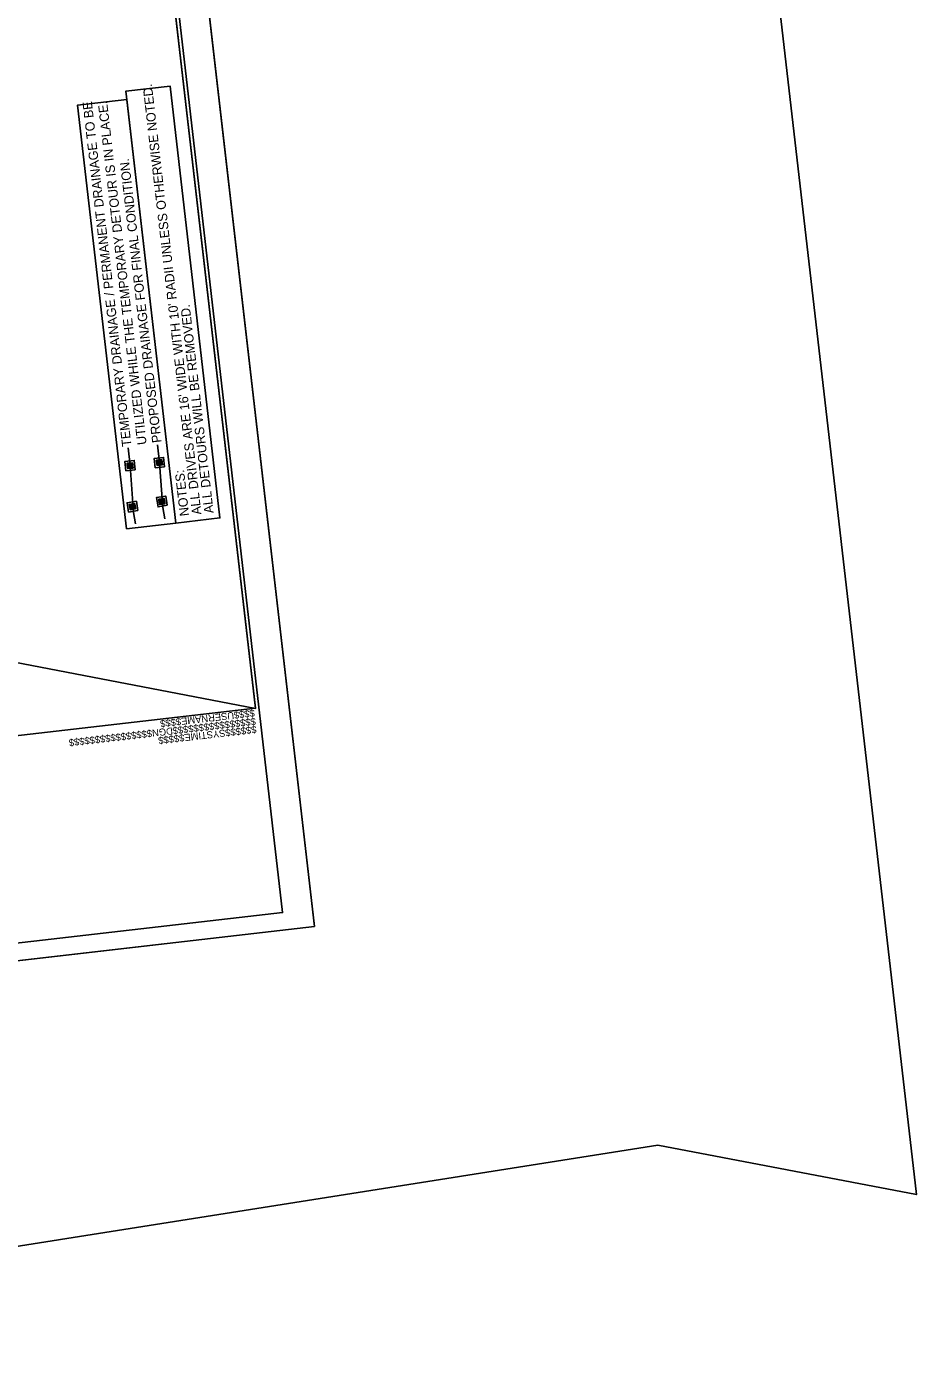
# Model space of a CAD drawing. Extents: x 477607 to 479438, y 495543 to 499482.
# Drawn here: x 478677 to 479342, y 495543 to 496535 of the extents above; entities that cross this region are included whole.
import ezdxf

# ---------------------------------------------------------------- set-up
doc = ezdxf.new("R2010")
doc.units = 0
for name, color, linetype in [('Old_Level_41', 7, 'Continuous'), ('Prop Drainage Structure CELL', 7, 'Continuous'), ('Prop DSN Text', 7, 'Continuous'), ('Prop Grid Mask', 7, 'Continuous'), ('Sheet Border Standard 30in CELL', 7, 'Continuous'), ('Sheet Cutting Line CELL', 7, 'Continuous'), ('Sheet Data Field CELL', 7, 'Continuous'), ('Sheet Layout Plan Border', 7, 'Continuous'), ('Sheet Plan CELL', 7, 'Continuous'), ('Sheet Plot Border Inside CELL', 7, 'Continuous'), ('Sheet Plot Border Outside CELL', 7, 'Continuous')]:
    doc.layers.add(name, color=color, linetype=linetype)

msp = doc.modelspace()

# ---------------------------------------------------------------- linework, layer by layer
at = {"layer": 'Old_Level_41'}
for p, q in [((478776.71, 496209.67), (478775.3, 496223.03)), ((478774.72, 496209.46), (478774.72, 496209.46)), ((478776.59, 496210.83), (478776.59, 496210.83)), ((478776.71, 496209.67), (478776.71, 496209.67)), ((478779.3, 496176.15), (478776.77, 496209.18)), ((478776.84, 496208.51), (478776.84, 496208.51)), ((478778.7, 496209.88), (478778.7, 496209.88)), ((478776.58, 496180.26), (478776.58, 496180.26)), ((478778.36, 496181.74), (478778.36, 496181.74)), ((478778.56, 496180.59), (478778.56, 496180.59)), ((478778.75, 496179.44), (478778.75, 496179.44)), ((478780.71, 496167.74), (478779.3, 496176.15)), ((478780.53, 496180.92), (478780.53, 496180.92))]:
    msp.add_line(p, q, dxfattribs=at)
for points in [[(478780.56, 496206.55), (478773.6, 496205.82), (478772.87, 496212.78), (478779.83, 496213.52)], [(478778.91, 496207.89), (478774.93, 496207.47), (478774.52, 496211.45), (478778.49, 496211.87)], [(478782.59, 496177.72), (478775.68, 496176.56), (478774.53, 496183.47), (478781.43, 496184.62)], [(478780.86, 496178.95), (478776.91, 496178.29), (478776.25, 496182.23), (478780.2, 496182.89)]]:
    msp.add_lwpolyline(points, close=True, dxfattribs=at)
for points in [[(478778.83, 496208.72), (478774.85, 496208.3), (478774.6, 496210.62), (478778.58, 496211.04), (478778.83, 496208.72)], [(478778.76, 496208.77), (478774.9, 496208.37), (478774.67, 496210.56), (478778.52, 496210.97), (478778.76, 496208.77)], [(478776.82, 496208.58), (478774.91, 496208.38), (478774.68, 496210.55), (478776.59, 496210.75), (478776.82, 496208.58)], [(478775.64, 496210.19), (478774.81, 496210.11), (478774.79, 496210.38), (478775.61, 496210.46), (478775.64, 496210.19)], [(478775.68, 496209.81), (478774.85, 496209.72), (478774.83, 496209.99), (478775.65, 496210.08), (478775.68, 496209.81)], [(478775.72, 496209.43), (478774.89, 496209.34), (478774.87, 496209.61), (478775.69, 496209.7), (478775.72, 496209.43)], [(478775.76, 496209.04), (478774.93, 496208.96), (478774.91, 496209.23), (478775.74, 496209.31), (478775.76, 496209.04)], [(478775.78, 496208.93), (478774.95, 496208.84), (478774.98, 496208.57), (478775.8, 496208.66), (478775.78, 496208.93)], [(478776.55, 496210.29), (478775.73, 496210.2), (478775.7, 496210.47), (478776.53, 496210.56), (478776.55, 496210.29)], [(478776.59, 496209.91), (478775.77, 496209.82), (478775.74, 496210.09), (478776.57, 496210.18), (478776.59, 496209.91)], [(478776.63, 496209.52), (478775.81, 496209.44), (478775.78, 496209.71), (478776.61, 496209.79), (478776.63, 496209.52)], [(478776.68, 496209.14), (478775.85, 496209.05), (478775.82, 496209.32), (478776.65, 496209.41), (478776.68, 496209.14)], [(478776.69, 496209.03), (478775.86, 496208.94), (478775.89, 496208.67), (478776.72, 496208.76), (478776.69, 496209.03)], [(478778.74, 496208.78), (478776.84, 496208.58), (478776.61, 496210.76), (478778.52, 496210.96), (478778.74, 496208.78)], [(478777.57, 496210.4), (478776.74, 496210.31), (478776.71, 496210.58), (478777.54, 496210.67), (478777.57, 496210.4)], [(478777.61, 496210.01), (478776.78, 496209.93), (478776.75, 496210.2), (478777.58, 496210.28), (478777.61, 496210.01)], [(478777.65, 496209.63), (478776.82, 496209.54), (478776.79, 496209.81), (478777.62, 496209.9), (478777.65, 496209.63)], [(478777.69, 496209.25), (478776.86, 496209.16), (478776.83, 496209.43), (478777.66, 496209.52), (478777.69, 496209.25)], [(478777.73, 496208.86), (478776.9, 496208.78), (478776.87, 496209.05), (478777.7, 496209.13), (478777.73, 496208.86)], [(478778.48, 496210.49), (478777.65, 496210.41), (478777.62, 496210.68), (478778.45, 496210.76), (478778.48, 496210.49)], [(478778.52, 496210.11), (478777.69, 496210.02), (478777.66, 496210.29), (478778.49, 496210.38), (478778.52, 496210.11)], [(478778.56, 496209.73), (478777.73, 496209.64), (478777.7, 496209.91), (478778.53, 496210), (478778.56, 496209.73)], [(478778.6, 496209.34), (478777.77, 496209.26), (478777.74, 496209.53), (478778.57, 496209.61), (478778.6, 496209.34)], [(478778.64, 496208.96), (478777.81, 496208.87), (478777.79, 496209.14), (478778.61, 496209.23), (478778.64, 496208.96)], [(478780.72, 496179.77), (478776.78, 496179.11), (478776.39, 496181.41), (478780.34, 496182.07), (478780.72, 496179.77)], [(478780.65, 496179.82), (478776.83, 496179.18), (478776.46, 496181.36), (478780.28, 496182), (478780.65, 496179.82)], [(478778.73, 496179.51), (478776.84, 496179.19), (478776.47, 496181.35), (478778.36, 496181.67), (478778.73, 496179.51)], [(478777.45, 496181.05), (478776.63, 496180.91), (478776.59, 496181.18), (478777.41, 496181.32), (478777.45, 496181.05)], [(478777.52, 496180.67), (478776.7, 496180.53), (478776.65, 496180.8), (478777.47, 496180.94), (478777.52, 496180.67)], [(478777.58, 496180.29), (478776.76, 496180.15), (478776.71, 496180.42), (478777.54, 496180.56), (478777.58, 496180.29)], [(478777.64, 496179.91), (478776.82, 496179.77), (478776.78, 496180.04), (478777.6, 496180.18), (478777.64, 496179.91)], [(478777.66, 496179.8), (478776.84, 496179.66), (478776.89, 496179.39), (478777.71, 496179.53), (478777.66, 496179.8)], [(478778.36, 496181.2), (478777.54, 496181.07), (478777.49, 496181.33), (478778.31, 496181.47), (478778.36, 496181.2)], [(478778.42, 496180.82), (478777.6, 496180.68), (478777.56, 496180.95), (478778.38, 496181.09), (478778.42, 496180.82)], [(478778.49, 496180.44), (478777.66, 496180.3), (478777.62, 496180.57), (478778.44, 496180.71), (478778.49, 496180.44)], [(478778.55, 496180.06), (478777.73, 496179.92), (478777.68, 496180.19), (478778.5, 496180.33), (478778.55, 496180.06)], [(478778.57, 496179.95), (478777.75, 496179.81), (478777.79, 496179.54), (478778.61, 496179.68), (478778.57, 496179.95)], [(478780.64, 496179.83), (478778.75, 496179.51), (478778.39, 496181.67), (478780.28, 496181.99), (478780.64, 496179.83)], [(478779.36, 496181.37), (478778.54, 496181.23), (478778.5, 496181.5), (478779.32, 496181.64), (478779.36, 496181.37)], [(478779.43, 496180.99), (478778.61, 496180.85), (478778.56, 496181.12), (478779.38, 496181.26), (478779.43, 496180.99)], [(478779.49, 496180.61), (478778.67, 496180.47), (478778.63, 496180.74), (478779.45, 496180.88), (478779.49, 496180.61)], [(478779.56, 496180.23), (478778.73, 496180.09), (478778.69, 496180.36), (478779.51, 496180.5), (478779.56, 496180.23)], [(478779.62, 496179.85), (478778.8, 496179.71), (478778.75, 496179.98), (478779.57, 496180.12), (478779.62, 496179.85)], [(478780.27, 496181.52), (478779.45, 496181.38), (478779.4, 496181.65), (478780.22, 496181.79), (478780.27, 496181.52)], [(478780.33, 496181.14), (478779.51, 496181), (478779.47, 496181.27), (478780.29, 496181.41), (478780.33, 496181.14)], [(478780.4, 496180.76), (478779.57, 496180.62), (478779.53, 496180.89), (478780.35, 496181.03), (478780.4, 496180.76)], [(478780.46, 496180.38), (478779.64, 496180.24), (478779.59, 496180.51), (478780.42, 496180.65), (478780.46, 496180.38)], [(478780.52, 496180), (478779.7, 496179.86), (478779.66, 496180.13), (478780.48, 496180.27), (478780.52, 496180)]]:
    msp.add_lwpolyline(points, dxfattribs=at)
at = {"layer": 'Prop Drainage Structure CELL'}
for p, q in [((478754.82, 496207.37), (478753.41, 496220.73)), ((478752.83, 496207.16), (478752.83, 496207.16)), ((478754.7, 496208.53), (478754.7, 496208.53)), ((478754.82, 496207.37), (478754.82, 496207.37)), ((478757.36, 496172.31), (478754.82, 496207.23)), ((478754.94, 496206.21), (478754.94, 496206.21)), ((478756.81, 496207.58), (478756.81, 496207.58)), ((478754.65, 496176.42), (478754.65, 496176.42)), ((478756.43, 496177.9), (478756.43, 496177.9)), ((478756.62, 496176.75), (478756.62, 496176.75)), ((478758.59, 496177.08), (478758.59, 496177.08)), ((478756.81, 496175.6), (478756.81, 496175.6)), ((478758.77, 496163.9), (478757.36, 496172.31))]:
    msp.add_line(p, q, dxfattribs=at)
for points in [[(478758.67, 496204.25), (478751.71, 496203.52), (478750.97, 496210.48), (478757.93, 496211.21)], [(478757.02, 496205.59), (478753.04, 496205.17), (478752.62, 496209.15), (478756.6, 496209.57)], [(478760.65, 496173.88), (478753.74, 496172.72), (478752.59, 496179.63), (478759.49, 496180.78)], [(478758.92, 496175.11), (478754.98, 496174.45), (478754.32, 496178.39), (478758.26, 496179.06)]]:
    msp.add_lwpolyline(points, close=True, dxfattribs=at)
for points in [[(478756.93, 496206.42), (478752.95, 496206), (478752.71, 496208.32), (478756.69, 496208.74), (478756.93, 496206.42)], [(478756.86, 496206.47), (478753.01, 496206.07), (478752.78, 496208.26), (478756.63, 496208.67), (478756.86, 496206.47)], [(478754.92, 496206.28), (478753.02, 496206.08), (478752.79, 496208.25), (478754.69, 496208.45), (478754.92, 496206.28)], [(478753.75, 496207.89), (478752.92, 496207.81), (478752.89, 496208.07), (478753.72, 496208.16), (478753.75, 496207.89)], [(478753.79, 496207.51), (478752.96, 496207.42), (478752.93, 496207.69), (478753.76, 496207.78), (478753.79, 496207.51)], [(478753.83, 496207.13), (478753, 496207.04), (478752.97, 496207.31), (478753.8, 496207.4), (478753.83, 496207.13)], [(478753.87, 496206.74), (478753.04, 496206.66), (478753.01, 496206.92), (478753.84, 496207.01), (478753.87, 496206.74)], [(478753.88, 496206.63), (478753.05, 496206.54), (478753.08, 496206.27), (478753.91, 496206.36), (478753.88, 496206.63)], [(478754.66, 496207.99), (478753.83, 496207.9), (478753.8, 496208.17), (478754.63, 496208.26), (478754.66, 496207.99)], [(478754.7, 496207.61), (478753.87, 496207.52), (478753.84, 496207.79), (478754.67, 496207.87), (478754.7, 496207.61)], [(478754.74, 496207.22), (478753.91, 496207.13), (478753.88, 496207.4), (478754.71, 496207.49), (478754.74, 496207.22)], [(478754.78, 496206.84), (478753.95, 496206.75), (478753.92, 496207.02), (478754.75, 496207.11), (478754.78, 496206.84)], [(478754.79, 496206.73), (478753.96, 496206.64), (478753.99, 496206.37), (478754.82, 496206.46), (478754.79, 496206.73)], [(478756.85, 496206.48), (478754.94, 496206.28), (478754.71, 496208.46), (478756.62, 496208.66), (478756.85, 496206.48)], [(478755.67, 496208.1), (478754.85, 496208.01), (478754.82, 496208.28), (478755.65, 496208.37), (478755.67, 496208.1)], [(478755.71, 496207.71), (478754.89, 496207.63), (478754.86, 496207.89), (478755.69, 496207.98), (478755.71, 496207.71)], [(478755.76, 496207.33), (478754.93, 496207.24), (478754.9, 496207.51), (478755.73, 496207.6), (478755.76, 496207.33)], [(478755.8, 496206.95), (478754.97, 496206.86), (478754.94, 496207.13), (478755.77, 496207.22), (478755.8, 496206.95)], [(478755.84, 496206.56), (478755.01, 496206.48), (478754.98, 496206.74), (478755.81, 496206.83), (478755.84, 496206.56)], [(478756.59, 496208.19), (478755.76, 496208.1), (478755.73, 496208.37), (478756.56, 496208.46), (478756.59, 496208.19)], [(478756.63, 496207.81), (478755.8, 496207.72), (478755.77, 496207.99), (478756.6, 496208.08), (478756.63, 496207.81)], [(478756.67, 496207.43), (478755.84, 496207.34), (478755.81, 496207.61), (478756.64, 496207.69), (478756.67, 496207.43)], [(478756.71, 496207.04), (478755.88, 496206.95), (478755.85, 496207.22), (478756.68, 496207.31), (478756.71, 496207.04)], [(478756.75, 496206.66), (478755.92, 496206.57), (478755.89, 496206.84), (478756.72, 496206.93), (478756.75, 496206.66)], [(478758.78, 496175.93), (478754.84, 496175.27), (478754.45, 496177.57), (478758.4, 496178.23), (478758.78, 496175.93)], [(478758.71, 496175.98), (478754.89, 496175.34), (478754.53, 496177.52), (478758.35, 496178.16), (478758.71, 496175.98)], [(478756.79, 496175.67), (478754.9, 496175.36), (478754.54, 496177.51), (478756.43, 496177.83), (478756.79, 496175.67)], [(478755.52, 496177.21), (478754.7, 496177.07), (478754.65, 496177.34), (478755.47, 496177.48), (478755.52, 496177.21)], [(478755.58, 496176.83), (478754.76, 496176.69), (478754.71, 496176.96), (478755.54, 496177.1), (478755.58, 496176.83)], [(478755.65, 496176.45), (478754.82, 496176.31), (478754.78, 496176.58), (478755.6, 496176.72), (478755.65, 496176.45)], [(478755.71, 496176.07), (478754.89, 496175.93), (478754.84, 496176.2), (478755.66, 496176.34), (478755.71, 496176.07)], [(478755.73, 496175.96), (478754.91, 496175.82), (478754.95, 496175.55), (478755.77, 496175.69), (478755.73, 496175.96)], [(478756.42, 496177.36), (478755.6, 496177.23), (478755.56, 496177.49), (478756.38, 496177.63), (478756.42, 496177.36)], [(478756.49, 496176.98), (478755.66, 496176.85), (478755.62, 496177.11), (478756.44, 496177.25), (478756.49, 496176.98)], [(478756.55, 496176.6), (478755.73, 496176.47), (478755.68, 496176.73), (478756.5, 496176.87), (478756.55, 496176.6)], [(478756.61, 496176.22), (478755.79, 496176.09), (478755.75, 496176.35), (478756.57, 496176.49), (478756.61, 496176.22)], [(478756.63, 496176.11), (478755.81, 496175.97), (478755.85, 496175.71), (478756.68, 496175.84), (478756.63, 496176.11)], [(478758.7, 496175.99), (478756.81, 496175.68), (478756.45, 496177.83), (478758.34, 496178.15), (478758.7, 496175.99)], [(478757.43, 496177.53), (478756.61, 496177.39), (478756.56, 496177.66), (478757.38, 496177.8), (478757.43, 496177.53)], [(478757.49, 496177.15), (478756.67, 496177.01), (478756.63, 496177.28), (478757.45, 496177.42), (478757.49, 496177.15)], [(478757.56, 496176.77), (478756.73, 496176.63), (478756.69, 496176.9), (478757.51, 496177.04), (478757.56, 496176.77)], [(478757.62, 496176.39), (478756.8, 496176.25), (478756.75, 496176.52), (478757.57, 496176.66), (478757.62, 496176.39)], [(478757.68, 496176.01), (478756.86, 496175.87), (478756.82, 496176.14), (478757.64, 496176.28), (478757.68, 496176.01)], [(478758.33, 496177.68), (478757.51, 496177.55), (478757.47, 496177.81), (478758.29, 496177.95), (478758.33, 496177.68)], [(478758.4, 496177.3), (478757.57, 496177.17), (478757.53, 496177.43), (478758.35, 496177.57), (478758.4, 496177.3)], [(478758.46, 496176.92), (478757.64, 496176.79), (478757.59, 496177.05), (478758.42, 496177.19), (478758.46, 496176.92)], [(478758.52, 496176.54), (478757.7, 496176.41), (478757.66, 496176.67), (478758.48, 496176.81), (478758.52, 496176.54)], [(478758.59, 496176.16), (478757.77, 496176.03), (478757.72, 496176.29), (478758.54, 496176.43), (478758.59, 496176.16)]]:
    msp.add_lwpolyline(points, dxfattribs=at)
at = {"layer": 'Prop Grid Mask'}
for points in [[(478788.93, 496164.48), (478751.72, 496487.13), (478784.72, 496490.94), (478821.92, 496168.28)], [(478752.07, 496160.23), (478715.58, 496476.7), (478752.44, 496480.95), (478788.93, 496164.48)]]:
    msp.add_lwpolyline(points, close=True, dxfattribs=at)
at = {"layer": 'Sheet Border Standard 30in CELL'}
msp.add_lwpolyline([(477633.61, 497396.04), (477805.43, 495905.92), (478848.52, 496026.19), (478676.7, 497516.31)], close=True, dxfattribs=at)
at = {"layer": 'Sheet Cutting Line CELL'}
for p, q in [((478892.48, 495863.15), (478699.59, 497536.07)), ((477799.72, 495737.15), (478892.48, 495863.15))]:
    msp.add_line(p, q, dxfattribs=at)
at = {"layer": 'Sheet Layout Plan Border'}
for points in [[(478060.61, 495968.97), (478655.26, 496063.07), (478848.53, 496026.02), (478736, 497002.06), (478709.93, 496998.31), (478420.13, 496964.9), (478384.13, 497277.1), (478673.93, 497310.52), (478699.76, 497316.34), (478696.24, 497346.89), (478616.75, 497337.72), (478607.5, 497417.87), (478188.47, 497393.35), (477955.38, 497379.71), (477811.17, 497371.27), (477828.93, 497217.21), (477697.93, 497202.08), (477716.32, 497043.31), (477674.84, 497038.51), (477805.45, 495905.89)], [(478060.61, 495968.97), (478655.26, 496063.07), (478848.53, 496026.02), (478736, 497002.06), (478709.93, 496998.31), (478420.13, 496964.9), (478384.13, 497277.1), (478673.93, 497310.52), (478699.76, 497316.34), (478696.24, 497346.89), (478616.75, 497337.72), (478607.5, 497417.87), (478188.47, 497393.35), (477955.38, 497379.71), (477811.17, 497371.27), (477828.93, 497217.21), (477697.93, 497202.08), (477716.32, 497043.31), (477674.84, 497038.51), (477805.45, 495905.89)], [(478554.39, 495605.71), (479149.04, 495699.82), (479342.31, 495662.77), (479229.78, 496638.8), (479203.71, 496635.06), (478913.91, 496601.65), (478877.91, 496913.85), (479167.71, 496947.26), (479193.54, 496953.08), (479190.02, 496983.63), (479110.53, 496974.47), (479101.28, 497054.62), (478682.25, 497030.1), (478449.16, 497016.46), (478304.95, 497008.02), (478322.71, 496853.96), (478191.71, 496838.83), (478210.1, 496680.06), (478168.62, 496675.25), (478299.23, 495542.64)]]:
    msp.add_lwpolyline(points, close=True, dxfattribs=at)
at = {"layer": 'Sheet Plan CELL'}
for points in [[(477633.61, 497396.08), (477805.43, 495905.92), (478848.52, 496026.19), (478676.7, 497516.33)], [(478848.52, 496026.19), (477805.45, 495905.89), (477656.51, 497197.32), (477805.59, 497214.52), (477782.68, 497413.24), (478676.7, 497516.33)]]:
    msp.add_lwpolyline(points, close=True, dxfattribs=at)
at = {"layer": 'Sheet Plot Border Inside CELL'}
msp.add_lwpolyline([(477629.65, 497408.17), (477820.53, 495752.64), (478868.69, 495873.49), (478677.8, 497529.02)], close=True, dxfattribs=at)
at = {"layer": 'Sheet Plot Border Outside CELL'}
msp.add_lwpolyline([(477606.83, 497410.07), (477799.72, 495737.15), (478892.48, 495863.15), (478699.59, 497536.07)], close=True, dxfattribs=at)

# ---------------------------------------------------------------- texts
at = {"layer": 'Prop DSN Text'}
for s, p in [("ALL DRIVES ARE 16' WIDE WITH 10' RADII UNLESS OTHERWISE NOTED. ", (478808.16, 496171.06)), ('ALL DETOURS WILL BE REMOVED. ', (478817.28, 496172.11)), ('NOTES: ', (478799.05, 496170))]:
    msp.add_text(s, height=7, rotation=96.57729, dxfattribs=at).set_placement(p)
at = {"layer": 'Sheet Border Standard 30in CELL'}
for s, p in [('$$$$$$$$$$$$$$$$DGN$$$$$$$$$$$$$$$$', (478848.49, 496018.99)), ('$$$$USERNAME$$$$', (478847.67, 496025.23)), ('$$$$$$SYSTIME$$$$$', (478848.98, 496012.95))]:
    msp.add_text(s, height=5.25, rotation=186.57729, dxfattribs=at).set_placement(p)
at = {"layer": 'Sheet Data Field CELL'}
for s, p in [('TEMPORARY DRAINAGE / PERMANENT DRAINAGE TO BE ', (478755.9, 496221.96)), ('UTILIZED WHILE THE TEMPORARY DETOUR IS IN PLACE.', (478767.2, 496223.26)), ('PROPOSED DRAINAGE FOR FINAL CONDITION.', (478778.36, 496224.79))]:
    msp.add_text(s, height=7, rotation=96.57729, dxfattribs=at).set_placement(p)

doc.saveas('drawing.dxf')
